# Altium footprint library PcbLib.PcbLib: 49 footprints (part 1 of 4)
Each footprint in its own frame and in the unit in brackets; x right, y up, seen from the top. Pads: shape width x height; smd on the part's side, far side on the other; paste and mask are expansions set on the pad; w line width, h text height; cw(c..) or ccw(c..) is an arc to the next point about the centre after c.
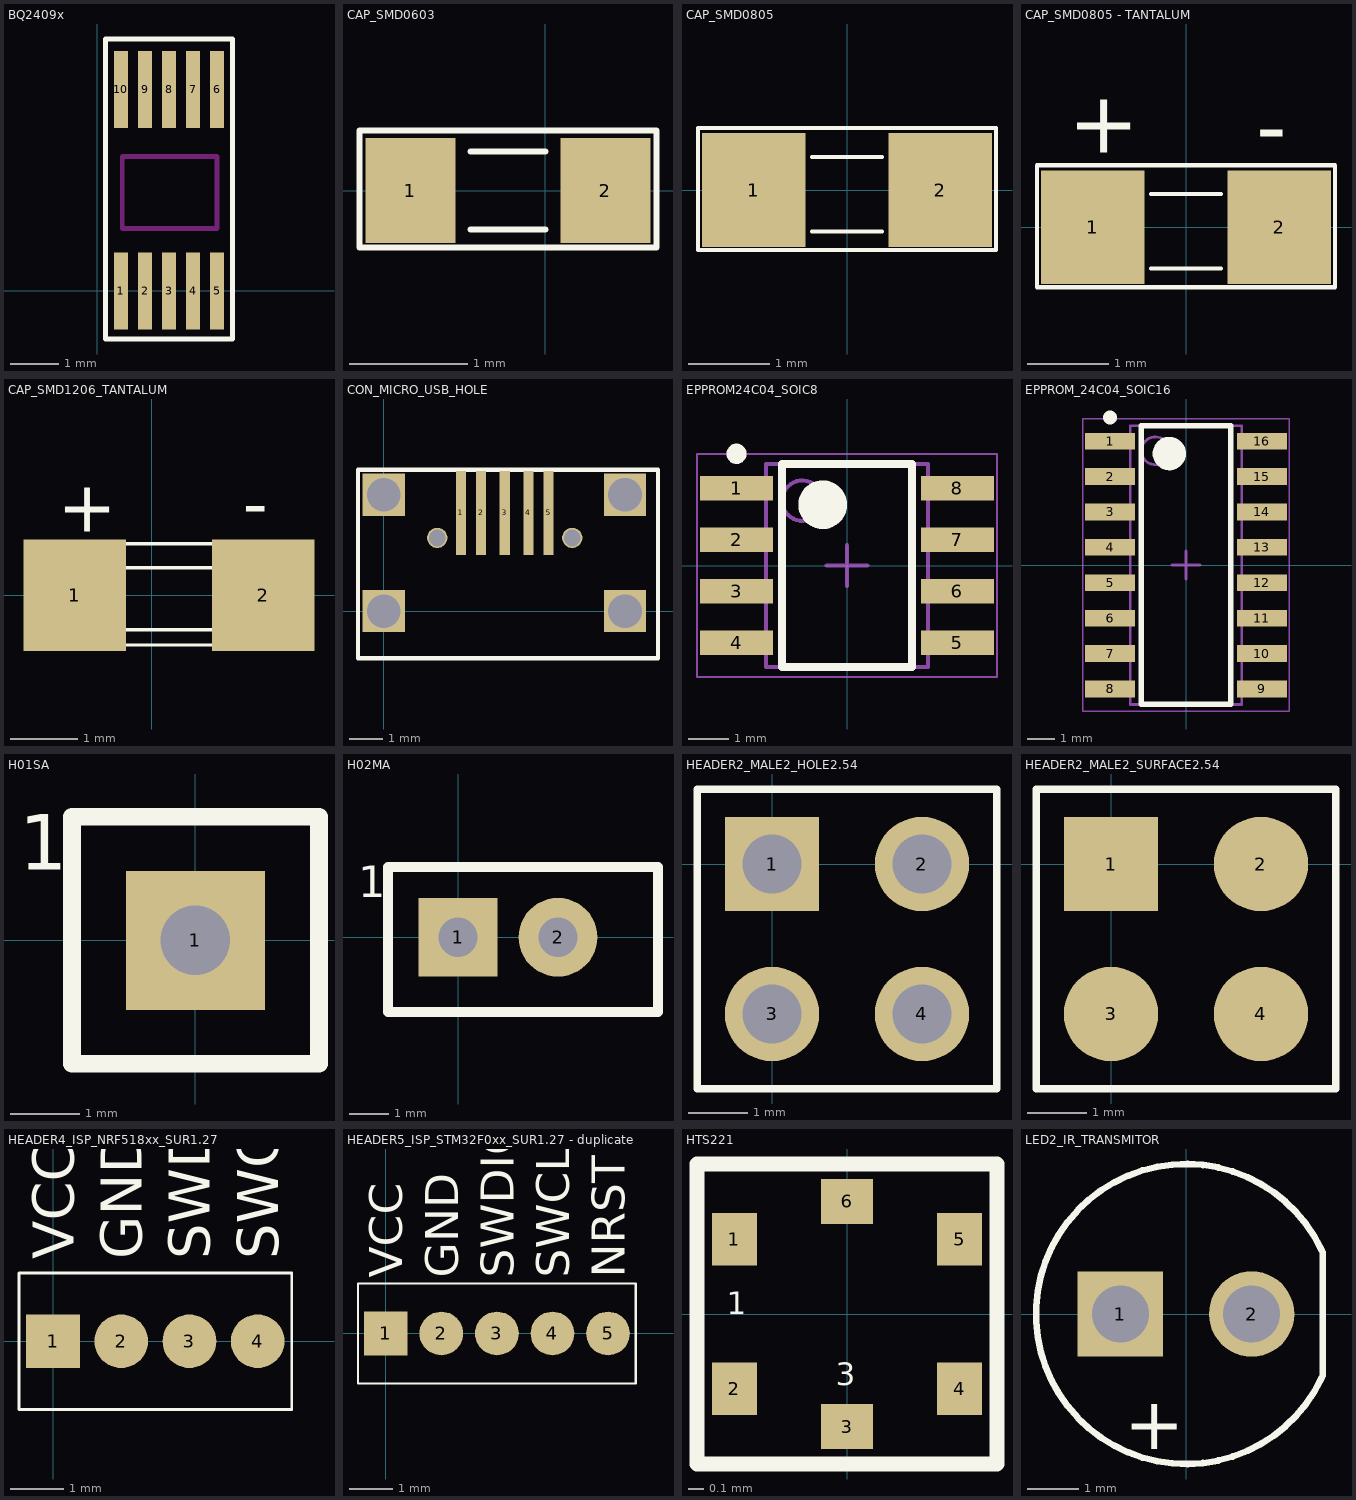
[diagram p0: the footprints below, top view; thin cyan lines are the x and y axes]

## BQ2409x [mm]
pads (10):
  rect 0.3x1.6 smd: 1(0.5,0) 2(1,0) 3(1.5,0) 4(2,0) 5(2.5,0) 6(2.5,4.2) 7(2,4.2) 8(1.5,4.2) 9(1,4.2) 10(0.5,4.2)
Top Overlay:
  lines w0.1: 0.175,-1 0.175,5.25 2.825,5.25 2.825,-1 0.175,-1
Keep-Out Layer:
  lines w0.1: 0.525,1.3 2.5,1.3 2.5,2.8 1.7,2.8 0.525,2.8 0.525,1.3

## CAP_SMD0603 [mil] "Compoment SMD 60x30mil"
height 50
pads (2):
  rect 30x35 smd: 1(-45,0) 2(20,0)
Top Overlay:
  lines w2: -25,-13 0,-13 ; -25,13 0,13 ; -62,-19 -62,20 37,20 37,-19 -0.25,-19 -52.75,-19 -62,-19
3D body "CircuitWorks-CAPACITOR 0603.step": height 32.68, standoff -1.18, extent -46.49,-16.92 16.51,16.93

## CAP_SMD0805 [mil] "Compoment SMD 80x50mil"
height 50
pads (2):
  rect 50x55 smd: 1(-45,0) 2(45,0)
Top Overlay:
  lines w2: -17,-20 17,-20 ; -17,16 17,16 ; -72,-29 -72,30 72,30 72,-29 -72,-29
3D body "User Library-CAPC2012X___.STEP": height 22.44, standoff 0, extent -39.36,-24.99 39.38,25

## CAP_SMD0805 - TANTALUM [mil] "Compoment SMD 80x50mil"
height 50
pads (2):
  rect 50x55 smd: 1(-45,0) 2(45,0)
Top Overlay:
  lines w2: -17,-20 17,-20 ; -17,16 17,16 ; -72,-29 -72,30 72,30 72,-29 -72,-29
  text "+" at -57,36 h30
  text "-" at 34,34 h30
3D body "User Library-CAPC2012X___.STEP": height 22.44, standoff 0, extent -39.36,-24.99 39.38,25

## CAP_SMD1206_TANTALUM [mil] "Compoment SMD 80x50mil"
height 50
pads (2):
  rect 60x65 smd: 1(-45,0) 2(65,0)
Top Overlay:
  lines w2: -17,-20 39,-20 ; -17,16 38,16 ; -72,-29 -72,30 72,30 72,-29 -72,-29
  text "+" at -55,37 h30
  text "-" at 53,39 h30
3D body "CircuitWorks-CAPACITOR 1206.step": height 64.68, standoff -0.68, extent -52.99,-31.42 72.99,30

## CON_MICRO_USB_HOLE [mm]
pads (11):
  rect 0.3x2.5 smd mask+0.05: 1(2.286,2.91) 2(2.886,2.91) 3(3.586,2.91) 4(4.286,2.91) 5(4.886,2.91)
  rect 1.25x1.25 hole 1 mask+0.05: ""(0,0) ""(0,3.45) ""(7.15,0) ""(7.15,3.45)
  round 0.6 hole 0.5 mask+0.05: ""(1.586,2.17) ""(5.586,2.17)
Top Overlay:
  lines w0.127: -0.762,-1.397 -0.762,4.191 8.128,4.191 8.128,-1.397 -0.762,-1.397
3D body "User Library-10104111.STEP": height 2.77, standoff -0.3, extent -0.717,-1.449 8.083,4.176

## EPPROM24C04_SOIC8 [mm]
height 1.35
pads (8):
  rect 1.8x0.6 smd: 1(-2.725,1.905) 2(-2.725,0.635) 3(-2.725,-0.635) 4(-2.725,-1.905) 5(2.725,-1.905) 6(2.725,-0.635) 7(2.725,0.635) 8(2.725,1.905)
Top Overlay:
  circle w0.25: c-2.725,2.755 r0.125
  circle w0.6: c-0.6,1.5 r0.3
  lines w0.2: -1.6,-2.5 -1.6,2.5 1.6,2.5 1.6,-2.5 -1.6,-2.5
Mechanical 13:
  circle w0.1: c-1.1,1.6 r0.5
  lines w0.1: -2,-2.5 -2,2.5 2,2.5 2,-2.5 -2,-2.5
Mechanical 15:
  lines w0.05: -3.7,-2.75 -3.7,2.75 3.7,2.75 3.7,-2.75 -3.7,-2.75
  lines w0.1: -0.5,0 0.5,0 ; 0,-0.5 0,0.5
3D body: height 1.35, standoff 0.1, extent -2,-2.5 2,2.5

## EPPROM_24C04_SOIC16 [mm] "EPPROM24 SURFACE SOIC16"
height 1.75
pads (16):
  rect 1.8x0.6 smd: 1(-2.725,4.445) 2(-2.725,3.175) 3(-2.725,1.905) 4(-2.725,0.635) 5(-2.725,-0.635) 6(-2.725,-1.905) 7(-2.725,-3.175) 8(-2.725,-4.445) 9(2.725,-4.445) 10(2.725,-3.175) 11(2.725,-1.905) 12(2.725,-0.635) 13(2.725,0.635) 14(2.725,1.905) 15(2.725,3.175) 16(2.725,4.445)
Top Overlay:
  circle w0.25: c-2.725,5.295 r0.125
  circle w0.6: c-0.6,4 r0.3
  lines w0.2: -1.6,-5 -1.6,5 1.6,5 1.6,-5 -1.6,-5
Mechanical 13:
  circle w0.1: c-1.1,4.1 r0.5
  lines w0.1: -2,-5 -2,5 2,5 2,-5 -2,-5
Mechanical 15:
  lines w0.05: -3.7,-5.25 -3.7,5.25 3.7,5.25 3.7,-5.25 -3.7,-5.25
  lines w0.1: -0.5,0 0.5,0 ; 0,-0.5 0,0.5
3D body: height 1.75, standoff 0.2, extent -2,-5 2,5

## H01SA [mm] "HEADER, SINGLE, DISTANCE = 100mil"
pads (1):
  rect 2x2 hole 1: 1(0,0)
Top Overlay:
  lines w0.254: -1.778,-1.778 1.778,-1.778 1.778,1.778 -1.778,1.778 -1.778,-1.778
  text "1" at -2.54,1.016 h0.8

## H02MA [mm] "HEADER, SINGLE, DISTANCE = 100mil"
pads (2):
  rect 2x2 hole 1: 1(0,0)
  round 2 hole 1: 2(2.54,0)
Top Overlay:
  lines w0.254: -1.778,-1.905 -1.778,1.778 5.08,1.778 5.08,-1.905 -1.778,-1.905
  text "1" at -2.54,1.016 h0.8

## HEADER2_MALE2_HOLE2.54 [mm] "HEADER, SINGLE, DISTANCE = 100mil"
pads (4):
  rect 1.6x1.6 hole 1: 1(0,0)
  round 1.6 hole 1: 2(2.54,0) 3(0,-2.54) 4(2.54,-2.54)
Top Overlay:
  lines w0.127: -1.27,-3.81 3.81,-3.81 3.81,1.27 -1.27,1.27 -1.27,-3.81
3D body "User Library-Header1x2.STEP": height 8.17, standoff -2.81, extent -1.27,-3.81 3.81,-1.27
3D body "User Library-Header1x2.STEP": height 8.17, standoff -2.81, extent -1.27,-1.27 3.81,1.27

## HEADER2_MALE2_SURFACE2.54 [mm] "HEADER, SINGLE, DISTANCE = 100mil"
pads (4):
  rect 1.6x1.6 smd: 1(0,0)
  round 1.6 smd: 2(2.54,0) 3(0,-2.54) 4(2.54,-2.54)
Top Overlay:
  lines w0.127: -1.27,-3.81 3.81,-3.81 3.81,1.27 -1.27,1.27 -1.27,-3.81
3D body "User Library-Header1x2.STEP": height 8.17, standoff -2.81, extent -1.27,-3.81 3.81,-1.27
3D body "User Library-Header1x2.STEP": height 8.17, standoff -2.81, extent -1.27,-1.27 3.81,1.27

## HEADER4_ISP_NRF518xx_SUR1.27 [mm] "HEADER, SINGLE, DISTANCE = 100mil"
pads (4):
  rect 1x1 smd: 1(0,0)
  round 1 smd: 2(1.27,0) 3(2.54,0) 4(3.81,0)
Top Overlay:
  lines w0.051: -0.635,-1.27 4.445,-1.27 4.445,1.27 -0.635,1.27 -0.635,-1.27
  text "SWCLK" at 4.191,1.524 h0.76
  text "SWDIO" at 2.921,1.524 h0.76
  text "GND" at 1.651,1.524 h0.76
  text "VCC" at 0.381,1.524 h0.76
3D body "User Library-PinHeader1_27_2.STEP": height 5, standoff -2.3, extent 1.905,-1.2 4.445,1.2
3D body "User Library-PinHeader1_27_2.STEP": height 5, standoff -2.3, extent -0.635,-1.19 1.905,1.21

## HEADER5_ISP_STM32F0xx_SUR1.27 - duplicate [mm] "HEADER, SINGLE, DISTANCE = 100mil"
pads (5):
  rect 1x1 smd: 1(0,0)
  round 1 smd: 2(1.27,0) 3(2.54,0) 4(3.81,0) 5(5.08,0)
Top Overlay:
  lines w0.051: -0.635,-1.143 -0.635,1.143 5.715,1.143 5.715,-1.143 -0.635,-1.143
  text "VCC" at 0.381,1.27 h0.76
  text "GND" at 1.651,1.27 h0.76
  text "SWDIO" at 2.921,1.27 h0.76
  text "SWCLK" at 4.191,1.27 h0.76
  text "NRST" at 5.461,1.27 h0.76
3D body "User Library-PinHeader1_27_2.STEP": height 5, standoff -2.3, extent -0.635,-1.2 1.905,1.2
3D body "User Library-PinHeader1_27_2.STEP": height 5, standoff -2.3, extent 1.905,-1.2 4.445,1.2

## HTS221 [mm]
pads (6):
  rect 0.3x0.35 smd mask+0.05: 1(-0.75,0.5) 2(-0.75,-0.5) 4(0.75,-0.5) 5(0.75,0.5)
  rect 0.35x0.3 smd mask+0.05: 3(0,-0.75) 6(0,0.75)
Top Overlay:
  lines w0.1: -1,-1 -1,1 1,1 1,-1 -1,-1
  text "3" at -0.075,-0.475 h0.15
  text "1" at -0.8,0 h0.15

## LED2_IR_TRANSMITOR [mil] "LED phi 5mm"
height 649.61
pads (2):
  rect 65x65 hole 43.31: 1(-50,0)
  round 65 hole 43.31: 2(50,0)
Top Overlay:
  lines w5: 103.49,-48.23 cw(c0,0) 103.49,48.23 ; 104,-47 104,46.9
  text "+" at -47,-103 h40
3D body "User Library-LED5MM.step": height 496.06, standoff -118.11, extent -116.14,-118.13 116.14,114.15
